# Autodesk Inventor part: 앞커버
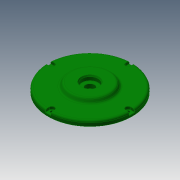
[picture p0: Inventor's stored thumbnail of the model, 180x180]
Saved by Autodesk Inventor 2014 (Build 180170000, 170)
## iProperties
Created: 2016-11
Part Number: 앞커버
Material: 알루미늄 6061
Document SubType Name: Modeling
Designer: mduedu
Density: 2.71 g/cm^3
Mass: 394.828 g
Surface Area: 366.341 cm^2
Volume: 145.693 cm^3
Appearance: 진녹색
Author: mduedu
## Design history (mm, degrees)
sketch "스케치1"
  geometry: L1 (22, -12.5)-(22, -30); L2 (22, -30)-(16, -33.464); L3 (16, -33.464)-(16, -65); L4 (16, -65)-(8, -65); L5 (8, -65)-(8, -53); L6 (8, -53)-(0, -53); L7 (0, -53)-(0, -14); L8 (0, 0)-(22, 0); L9 (8, -14)-(8, -7); L10 (8, -7)-(14.5, -7); L11 (14.5, -7)-(14.5, -12.5); L12 (0, -14)-(8, -14); L13 (14.5, -12.5)-(22, -12.5)
  constraints: 26 end point, 8 parallel, 3 perpendicular, 2 horizontal, 2 vertical alignment, 1 collinear
  dimensions: "d0" = 8 distance of L5.end L6.end; "d2" = 8 distance of L3.end L4.end; "d3" = 6 distance between parallel lines of L1 L3; "d4" = 120 deg angle of L3 L2; "d5" = 7.5 distance of L11.end L1.start; "d6" = 60 diameter of L1.end L8; "d7" = 14 diameter of L10 L8; "d8" = 28 diameter of L12 L8; "d9" = 25 diameter of L13 L8; "d10" = 106 diameter of L6 L8; "d11" = 130 diameter of L4 L8
revolve "회전1" sketch "스케치1" stored, may be unused: angle "d12" = 90 deg
fillet "모깎기1" dims "d13" = 0.3
fillet "모깎기2" dims "d14" = 3
chamfer "모따기1" distance "d15" = 1; stored, may be unused: second distance "d16" = 2, angle "d17" = 45 deg
fillet "모깎기3" dims "d18" = 0.3
chamfer "모따기2" distance "d36" = 2; stored, may be unused: second distance "d37" = 2, angle "d38" = 30 deg
sketch "스케치3"
  geometry: C1 r 65 at (0, 0) reference; A1 r 59 centre (0, 0) between (0, 59) and (59, 0); 2 further points
  constraints: 4 point on circle, 2 horizontal alignment, 2 vertical alignment, 1 centre point, 1 coincident
  dimensions: "d33" = 118 diameter of A1
sketch "스케치4"
  geometry: 4 further points
  constraints: 4 other
hole "구멍2" sketch "스케치4" at (0, 59), (-59, 0), (59, 0), (0, -59) diameter "d39" = 4.5; stored, may be unused: countersink angle "d43" = 90 deg, drill point angle "d45" = 0 deg; dims "d40" = 6, "d41" = 8, "d42" = 4.6, "d44" = 8
sketch "스케치6"
  geometry: L1 (-4, 5.877)-(-4, 0); L2 (4, 5.877)-(4, 0); A1 r 4 centre (0, 0) between (-2.712, 2.941) and (2.712, 2.941) reference; A2 r 65 centre (0, -59) between (-4, 5.877) and (4, 5.877) reference; 1 further point
  constraints: 4 end point, 4 point on circle, 2 tangent, 2 vertical
extrude "돌출2" cut sketch "스케치6" stored distance "d51" = 10; taper "d52" = 0 deg
fillet "모깎기5" dims "d56" = 0.3
fillet "모깎기6" dims "d57" = 0.3
sketch "스케치5"
  geometry: C1 r 22 at (0, 0); C2 r 45 at (0, 0); 1 further point
  constraints: 2 centre point, 2 coincident
  dimensions: "d46" = 44 diameter of C1; "d47" = 90 diameter of C2
extrude "돌출1" cut sketch "스케치5" distance "d48" = 8; taper "d49" = 0 deg
fillet "모깎기4" dims "d50" = 3
node "솔리드1"
pattern_circular "원형 패턴1" dims angle "d54" = 360 deg
pattern_circular "원형 패턴2" dims angle "d59" = 360 deg
pattern_circular "원형 패턴3" dims angle "d62" = 360 deg
